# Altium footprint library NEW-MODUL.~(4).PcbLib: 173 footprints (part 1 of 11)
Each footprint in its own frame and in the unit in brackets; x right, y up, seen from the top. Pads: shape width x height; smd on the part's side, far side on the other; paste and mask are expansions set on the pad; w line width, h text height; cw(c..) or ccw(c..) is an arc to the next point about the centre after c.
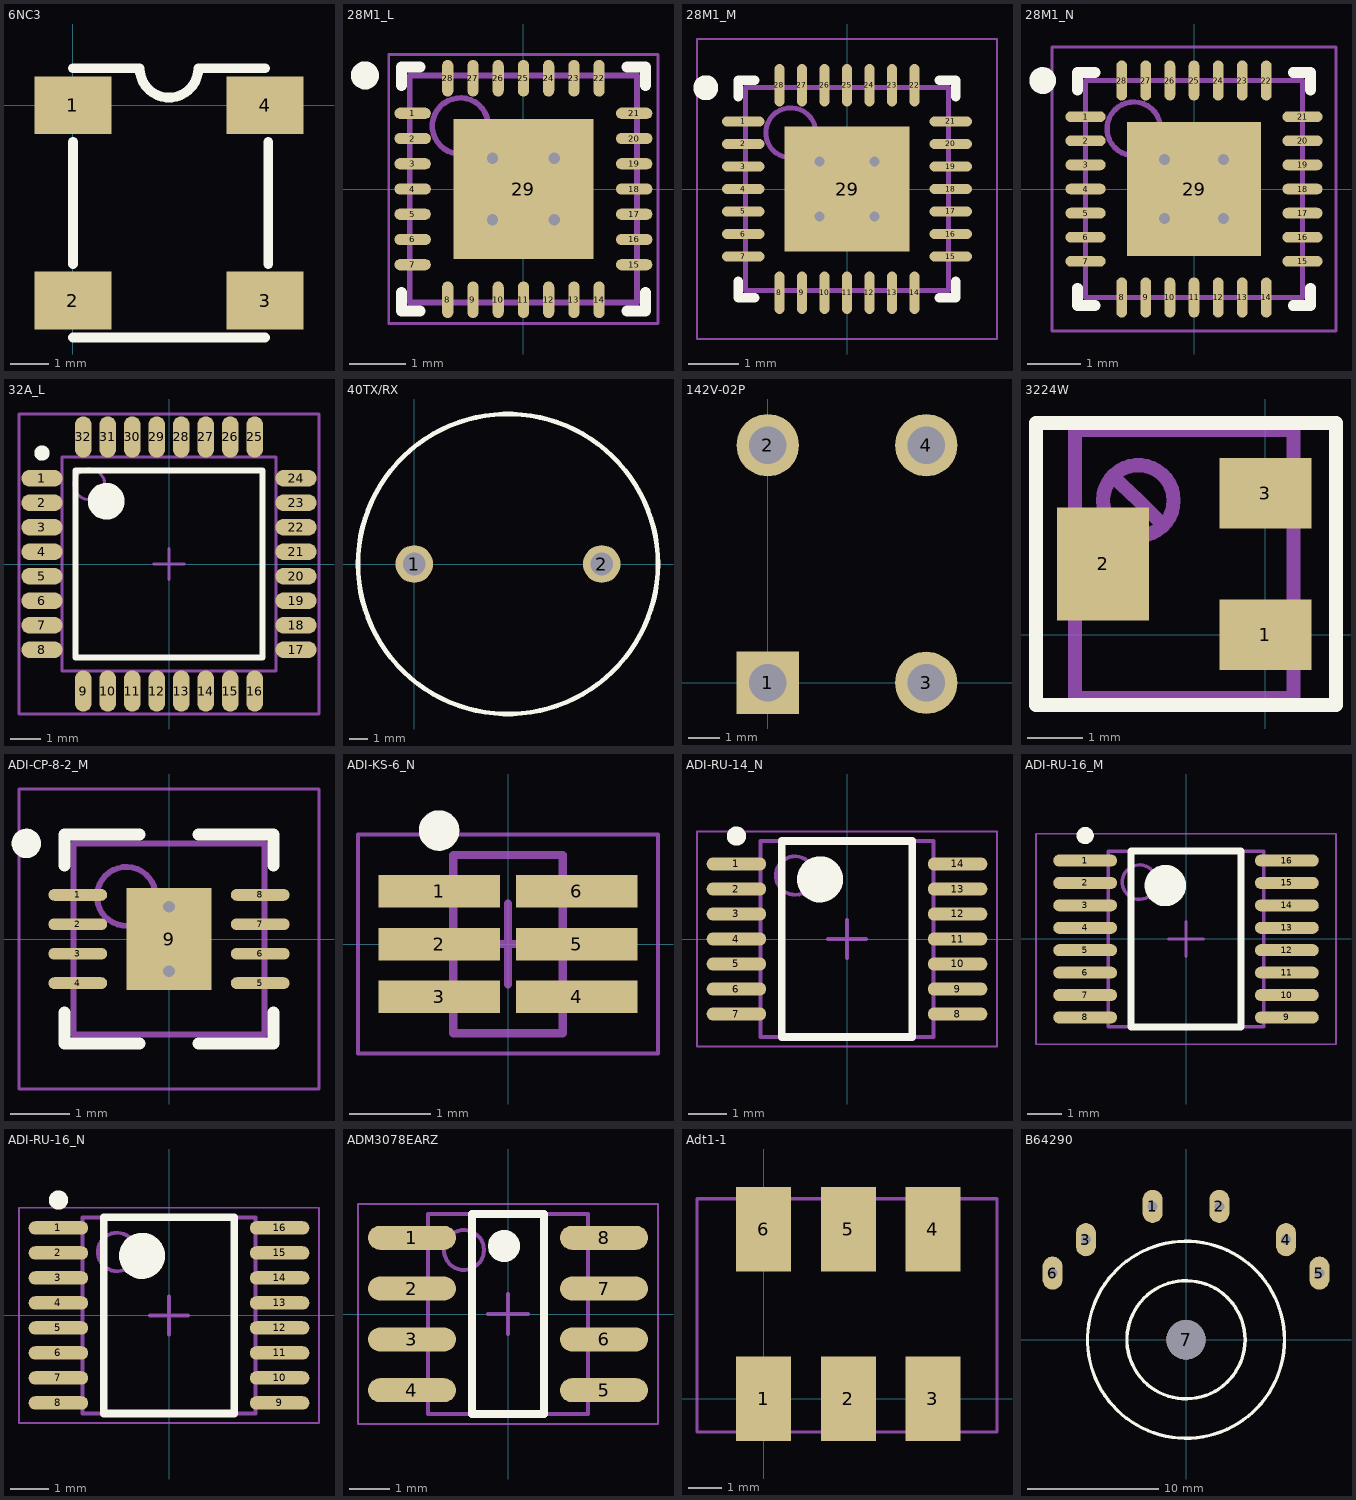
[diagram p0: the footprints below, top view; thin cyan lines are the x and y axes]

## 6NC3 [mm]
pads (4):
  rect 2x1.5 smd: 1(0,0) 2(0,-5.08) 3(5,-5.08) 4(5,0)
Top Overlay:
  lines w0.254: 0,-6.04 5,-6.04 ; 0,-4.127 0,-0.953 ; 0,0.96 1.738,0.96 ccw(c2.5,0.96) 3.262,0.96 5,0.96 ; 5.08,-4.127 5.08,-0.953
3D body "User Library-VX3-Quartz-Oscillator.step": height 1.62, standoff 0.02, extent 0.04,-6.04 5.04,0.96

## 28M1_L [mm] "QFN, 28-Leads, Body 4x4mm, Pitch 0.45mm, Thermal Pad 2.5x2.5mm, IPC High Density"
height 1
pads (29):
  oval 0.65x0.2 smd: 1(-1.975,1.35) 2(-1.975,0.9) 3(-1.975,0.45) 4(-1.975,0) 5(-1.975,-0.45) 6(-1.975,-0.9) 7(-1.975,-1.35) 15(1.975,-1.35) 16(1.975,-0.9) 17(1.975,-0.45) 18(1.975,0) 19(1.975,0.45) 20(1.975,0.9) 21(1.975,1.35)
  oval 0.2x0.65 smd: 8(-1.35,-1.975) 9(-0.9,-1.975) 10(-0.45,-1.975) 11(0,-1.975) 12(0.45,-1.975) 13(0.9,-1.975) 14(1.35,-1.975) 22(1.35,1.975) 23(0.9,1.975) 24(0.45,1.975) 25(0,1.975) 26(-0.45,1.975) 27(-0.9,1.975) 28(-1.35,1.975)
  rect 2.5x2.5 smd: 29(0,0)
via -0.55,0.55 diameter 0.5 hole 0.2
via 0.55,0.55 diameter 0.5 hole 0.2
via -0.55,-0.55 diameter 0.5 hole 0.2
via 0.55,-0.55 diameter 0.5 hole 0.2
Top Overlay:
  circle w0.25: c-2.825,2.025 r0.125
  lines w0.2: -2.175,-1.85 -2.175,-2.175 -1.85,-2.175 ; -2.175,1.85 -2.175,2.175 -1.85,2.175 ; 1.85,-2.175 2.175,-2.175 2.175,-1.85 ; 1.85,2.175 2.175,2.175 2.175,1.85
Mechanical 13:
  circle w0.1: c-1.125,1.125 r0.5
  lines w0.1: -2.025,-2.025 -2.025,2.025 2.025,2.025 2.025,-2.025 -2.025,-2.025
Mechanical 15:
  lines w0.05: -2.4,-2.4 -2.4,2.4 2.4,2.4 2.4,-2.4 -2.4,-2.4
  lines w0.1: -0.5,0 0.5,0 ; 0,-0.5 0,0.5
3D body: height 1, standoff 0, extent -2.025,-2.025 2.025,2.025

## 28M1_M [mm] "QFN, 28-Leads, Body 4x4mm, Pitch 0.45mm, Thermal Pad 2.5x2.5mm, IPC Low Density"
height 1
pads (29):
  oval 0.85x0.2 smd: 1(-2.075,1.35) 2(-2.075,0.9) 3(-2.075,0.45) 4(-2.075,0) 5(-2.075,-0.45) 6(-2.075,-0.9) 7(-2.075,-1.35) 15(2.075,-1.35) 16(2.075,-0.9) 17(2.075,-0.45) 18(2.075,0) 19(2.075,0.45) 20(2.075,0.9) 21(2.075,1.35)
  oval 0.2x0.85 smd: 8(-1.35,-2.075) 9(-0.9,-2.075) 10(-0.45,-2.075) 11(0,-2.075) 12(0.45,-2.075) 13(0.9,-2.075) 14(1.35,-2.075) 22(1.35,2.075) 23(0.9,2.075) 24(0.45,2.075) 25(0,2.075) 26(-0.45,2.075) 27(-0.9,2.075) 28(-1.35,2.075)
  rect 2.5x2.5 smd: 29(0,0)
via 0.55,-0.55 diameter 0.5 hole 0.2
via -0.55,-0.55 diameter 0.5 hole 0.2
via 0.55,0.55 diameter 0.5 hole 0.2
via -0.55,0.55 diameter 0.5 hole 0.2
Top Overlay:
  circle w0.25: c-2.825,2.025 r0.125
  lines w0.2: -2.175,-1.85 -2.175,-2.175 -1.85,-2.175 ; -2.175,1.85 -2.175,2.175 -1.85,2.175 ; 1.85,-2.175 2.175,-2.175 2.175,-1.85 ; 1.85,2.175 2.175,2.175 2.175,1.85
Mechanical 13:
  circle w0.1: c-1.125,1.125 r0.5
  lines w0.1: -2.025,-2.025 2.025,-2.025 2.025,2.025 -2.025,2.025 -2.025,-2.025
Mechanical 15:
  lines w0.05: -3,-3 3,-3 3,3 -3,3 -3,-3
  lines w0.1: -0.5,0 0.5,0 ; 0,-0.5 0,0.5
3D body: height 1, standoff 0, extent -2.025,-2.025 2.025,2.025

## 28M1_N [mm] "QFN, 28-Leads, Body 4x4mm, Pitch 0.45mm, Thermal Pad 2.5x2.5mm, IPC Medium Density"
height 1
pads (29):
  oval 0.75x0.2 smd: 1(-2.025,1.35) 2(-2.025,0.9) 3(-2.025,0.45) 4(-2.025,0) 5(-2.025,-0.45) 6(-2.025,-0.9) 7(-2.025,-1.35) 15(2.025,-1.35) 16(2.025,-0.9) 17(2.025,-0.45) 18(2.025,0) 19(2.025,0.45) 20(2.025,0.9) 21(2.025,1.35)
  oval 0.2x0.75 smd: 8(-1.35,-2.025) 9(-0.9,-2.025) 10(-0.45,-2.025) 11(0,-2.025) 12(0.45,-2.025) 13(0.9,-2.025) 14(1.35,-2.025) 22(1.35,2.025) 23(0.9,2.025) 24(0.45,2.025) 25(0,2.025) 26(-0.45,2.025) 27(-0.9,2.025) 28(-1.35,2.025)
  rect 2.5x2.5 smd: 29(0,0)
via -0.55,0.55 diameter 0.5 hole 0.2
via 0.55,0.55 diameter 0.5 hole 0.2
via -0.55,-0.55 diameter 0.5 hole 0.2
via 0.55,-0.55 diameter 0.5 hole 0.2
Top Overlay:
  circle w0.25: c-2.825,2.025 r0.125
  lines w0.2: -2.175,-1.85 -2.175,-2.175 -1.85,-2.175 ; -2.175,1.85 -2.175,2.175 -1.85,2.175 ; 1.85,-2.175 2.175,-2.175 2.175,-1.85 ; 1.85,2.175 2.175,2.175 2.175,1.85
Mechanical 13:
  circle w0.1: c-1.125,1.125 r0.5
  lines w0.1: -2.025,-2.025 -2.025,2.025 2.025,2.025 2.025,-2.025 -2.025,-2.025
Mechanical 15:
  lines w0.05: -2.65,-2.65 -2.65,2.65 2.65,2.65 2.65,-2.65 -2.65,-2.65
  lines w0.1: -0.5,0 0.5,0 ; 0,-0.5 0,0.5
3D body: height 1, standoff 0, extent -2.025,-2.025 2.025,2.025

## 32A_L [mm] "32-Pin Thin Quad Flat Pack 0.8 mm Pitch, IPC High Density"
height 1.2
pads (32):
  oval 1.35x0.55 smd: 1(-4.15,2.8) 2(-4.15,2) 3(-4.15,1.2) 4(-4.15,0.4) 5(-4.15,-0.4) 6(-4.15,-1.2) 7(-4.15,-2) 8(-4.15,-2.8) 17(4.15,-2.8) 18(4.15,-2) 19(4.15,-1.2) 20(4.15,-0.4) 21(4.15,0.4) 22(4.15,1.2) 23(4.15,2) 24(4.15,2.8)
  oval 0.55x1.35 smd: 9(-2.8,-4.15) 10(-2,-4.15) 11(-1.2,-4.15) 12(-0.4,-4.15) 13(0.4,-4.15) 14(1.2,-4.15) 15(2,-4.15) 16(2.8,-4.15) 25(2.8,4.15) 26(2,4.15) 27(1.2,4.15) 28(0.4,4.15) 29(-0.4,4.15) 30(-1.2,4.15) 31(-2,4.15) 32(-2.8,4.15)
Top Overlay:
  circle w0.6: c-2.05,2.05 r0.3
  circle w0.25: c-4.15,3.625 r0.125
  lines w0.2: -3.05,-3.05 3.05,-3.05 3.05,3.05 -3.05,3.05 -3.05,-3.05
Mechanical 13:
  circle w0.1: c-2.6,2.6 r0.5
  lines w0.1: -3.5,-3.5 3.5,-3.5 3.5,3.5 -3.5,3.5 -3.5,-3.5
Mechanical 15:
  lines w0.1: -0.5,0 0.5,0 ; 0,-0.5 0,0.5 ; -4.9,-4.9 4.9,-4.9 4.9,4.9 -4.9,4.9 -4.9,-4.9
3D body "User Library-TQFP-32.STEP": height 1.48, standoff 0.02, extent -4.5,-4.5 4.5,4.5

## 40TX/RX [mm]
pads (2):
  round 2 hole 1.2: 1(0,0) 2(10,0)
Top Overlay:
  circle w0.254: c5,0 r8
3D body "User Library-400PT160 (1).step": height 17, standoff -5, extent -3.1,-8.1 13.1,8.1

## 142V-02P [mm]
pads (4):
  rect 2x2 hole 1.2: 1(0,0)
  round 2 hole 1.2: 2(0,7.62) 3(5.08,0) 4(5.08,7.62)
3D body "691401700002b.stp": height 14.01, standoff -3.14, extent -4.96,-4.244 7.58,8.756

## 3224W [mil]
pads (3):
  rect 65x50 smd: 1(0,0) 3(0,100)
  rect 65x80 smd: 2(-115,50)
Top Overlay:
  lines w10: -162.5,-50 50,-50 50,150 -162.5,150 -162.5,-50
Mechanical 1:
  lines w10: -108,112 -90,95 -73,78 ; -135,-45 20,-45 20,145 -135,145 -135,-45 ; -115,95 ccw(c-90,95) -65,95 ccw(c-90,95) -115,95
3D body "User Library-Bourns 3224W multiturn potentiometer x1.step": height 209.26, standoff 0.6, extent -136.77,-44.49 16.77,144.49

## ADI-CP-8-2_M [mm] "QFN, 8-Leads, Body 3x3mm, Pitch 0.5mm, Thermal Pad 1.45X1.74mm, IPC Low Density"
height 0.9
pads (9):
  oval 1x0.2 smd: 1(-1.55,0.75) 2(-1.55,0.25) 3(-1.55,-0.25) 4(-1.55,-0.75) 5(1.55,-0.75) 6(1.55,-0.25) 7(1.55,0.25) 8(1.55,0.75)
  rect 1.45x1.74 smd: 9(0,0)
via 0,0.55 diameter 0.5 hole 0.2
via 0,-0.55 diameter 0.5 hole 0.2
Top Overlay:
  circle w0.25: c-2.425,1.625 r0.125
  lines w0.2: -1.775,-1.25 -1.775,-1.775 -0.5,-1.775 ; -1.775,1.25 -1.775,1.775 -0.5,1.775 ; 0.5,-1.775 1.775,-1.775 1.775,-1.25 ; 0.5,1.775 1.775,1.775 1.775,1.25
Mechanical 13:
  circle w0.1: c-0.725,0.725 r0.5
  lines w0.1: -1.625,-1.625 -1.625,1.625 1.625,1.625 1.625,-1.625 -1.625,-1.625
Mechanical 15:
  lines w0.05: -2.55,-2.55 -2.55,2.55 2.55,2.55 2.55,-2.55 -2.55,-2.55
  lines w0.1: -0.5,0 0.5,0 ; 0,-0.5 0,0.5
3D body "User Library-LFCSP-16.step": height 0.97, standoff -0.03, extent -1.51,-1.51 1.51,1.51

## ADI-KS-6_N [mm] "SOT23, 6-Leads, Body 2x1.25mm, Pitch 0.65mm, IPC Medium Density"
height 1.1
pads (6):
  rect 1.5x0.4 smd: 1(-0.85,0.65) 2(-0.85,0) 3(-0.85,-0.65) 4(0.85,-0.65) 5(0.85,0) 6(0.85,0.65)
Top Overlay:
  circle w0.25: c-0.85,1.4 r0.125
Mechanical 13:
  lines w0.1: -0.675,-1.1 -0.675,1.1 0.675,1.1 0.675,-1.1 -0.675,-1.1
Mechanical 15:
  lines w0.05: -1.85,-1.35 -1.85,1.35 1.85,1.35 1.85,-1.35 -1.85,-1.35
  lines w0.1: -0.5,0 0.5,0 ; 0,-0.5 0,0.5
3D body "User Library-SOT363-2.step": height 1.1, standoff 0, extent -1.2,-1.1 1.2,1.1

## ADI-RU-14_N [mm] "SOP, 14-Leads, Body 5x4.4mm, Pitch 0.65mm, IPC Medium Density"
height 1.2
pads (14):
  oval 1.55x0.35 smd: 1(-2.875,1.95) 2(-2.875,1.3) 3(-2.875,0.65) 4(-2.875,0) 5(-2.875,-0.65) 6(-2.875,-1.3) 7(-2.875,-1.95) 8(2.875,-1.95) 9(2.875,-1.3) 10(2.875,-0.65) 11(2.875,0) 12(2.875,0.65) 13(2.875,1.3) 14(2.875,1.95)
Top Overlay:
  circle w0.25: c-2.875,2.675 r0.125
  circle w0.6: c-0.7,1.55 r0.3
  lines w0.2: -1.7,-2.55 -1.7,2.55 1.7,2.55 1.7,-2.55 -1.7,-2.55
Mechanical 13:
  circle w0.1: c-1.35,1.65 r0.5
  lines w0.1: -2.25,-2.55 -2.25,2.55 2.25,2.55 2.25,-2.55 -2.25,-2.55
Mechanical 15:
  lines w0.05: -3.9,-2.8 -3.9,2.8 3.9,2.8 3.9,-2.8 -3.9,-2.8
  lines w0.1: -0.5,0 0.5,0 ; 0,-0.5 0,0.5
3D body "User Library-tssop14-2.step": height 1.2, standoff 0, extent -3.2,-2.55 3.2,2.55

## ADI-RU-16_M [mm] "SOP, 16-Leads, Body 5x4.4mm, Pitch 0.65mm, IPC Low Density"
height 1.2
pads (16):
  oval 1.85x0.35 smd: 1(-2.925,2.275) 2(-2.925,1.625) 3(-2.925,0.975) 4(-2.925,0.325) 5(-2.925,-0.325) 6(-2.925,-0.975) 7(-2.925,-1.625) 8(-2.925,-2.275) 9(2.925,-2.275) 10(2.925,-1.625) 11(2.925,-0.975) 12(2.925,-0.325) 13(2.925,0.325) 14(2.925,0.975) 15(2.925,1.625) 16(2.925,2.275)
Top Overlay:
  circle w0.6: c-0.6,1.55 r0.3
  circle w0.25: c-2.925,3 r0.125
  lines w0.2: -1.6,-2.55 1.6,-2.55 1.6,2.55 -1.6,2.55 -1.6,-2.55
Mechanical 13:
  circle w0.1: c-1.35,1.65 r0.5
  lines w0.1: -2.25,-2.55 2.25,-2.55 2.25,2.55 -2.25,2.55 -2.25,-2.55
Mechanical 15:
  lines w0.05: -4.35,-3.05 4.35,-3.05 4.35,3.05 -4.35,3.05 -4.35,-3.05
  lines w0.1: -0.5,0 0.5,0 ; 0,-0.5 0,0.5
3D body "User Library-TSSOP-16-1.step": height 1.1, standoff 0, extent -3.2,-2.5 3.2,2.5

## ADI-RU-16_N [mm] "SOP, 16-Leads, Body 5x4.4mm, Pitch 0.65mm, IPC Medium Density"
height 1.2
pads (16):
  oval 1.55x0.35 smd: 1(-2.875,2.275) 2(-2.875,1.625) 3(-2.875,0.975) 4(-2.875,0.325) 5(-2.875,-0.325) 6(-2.875,-0.975) 7(-2.875,-1.625) 8(-2.875,-2.275) 9(2.875,-2.275) 10(2.875,-1.625) 11(2.875,-0.975) 12(2.875,-0.325) 13(2.875,0.325) 14(2.875,0.975) 15(2.875,1.625) 16(2.875,2.275)
Top Overlay:
  circle w0.25: c-2.875,3 r0.125
  circle w0.6: c-0.7,1.55 r0.3
  lines w0.2: -1.7,-2.55 -1.7,2.55 1.7,2.55 1.7,-2.55 -1.7,-2.55
Mechanical 13:
  circle w0.1: c-1.35,1.65 r0.5
  lines w0.1: -2.25,-2.55 -2.25,2.55 2.25,2.55 2.25,-2.55 -2.25,-2.55
Mechanical 15:
  lines w0.05: -3.9,-2.8 -3.9,2.8 3.9,2.8 3.9,-2.8 -3.9,-2.8
  lines w0.1: -0.5,0 0.5,0 ; 0,-0.5 0,0.5
3D body: height 1.2, standoff 0.05, extent -2.25,-2.55 2.25,2.55

## ADM3078EARZ [mm]
pads (8):
  oval 2.2x0.6 smd: 1(-2.4,1.905) 2(-2.4,0.635) 3(-2.4,-0.635) 4(-2.4,-1.905) 5(2.4,-1.905) 6(2.4,-0.635) 7(2.4,0.635) 8(2.4,1.905)
Top Overlay:
  circle w0.4: c-0.1,1.7 r0.2
  lines w0.2: -0.9,-2.5 0.9,-2.5 0.9,2.5 -0.9,2.5 -0.9,-2.5
Mechanical 13:
  circle w0.1: c-1.1,1.6 r0.5
  lines w0.1: -2,-2.5 2,-2.5 2,2.5 -2,2.5 -2,-2.5
Mechanical 15:
  lines w0.05: -3.75,-2.75 3.75,-2.75 3.75,2.75 -3.75,2.75 -3.75,-2.75
  lines w0.1: -0.5,0 0.5,0 ; 0,-0.5 0,0.5
3D body: height 1.75, standoff 0.1, extent -2,-2.5 2,2.5

## Adt1-1 [mm]
pads (6):
  rect 1.65x2.54 smd: 1(0,0) 2(2.54,0) 3(5.08,0) 4(5.08,5.08) 5(2.54,5.08) 6(0,5.08)
Top Overlay:
  region: 5,0
Mechanical 15:
  lines w0.1: -2,-1 7,-1 7,6 -2,6 -2,-1

## B64290 [mil] "Трансформатор для дозиметра"
height 196.85
pads (7):
  oval 60x99.37 hole 30: 1(-100,400) 2(100,400) 3(-300,300) 4(300,300) 5(400,200) 6(-400,200)
  round 118.11 hole 118.11 unplated: 7(0,0)
Top Overlay:
  circle w10: c0,0 r295.28
  circle w10: c0,0 r177.17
